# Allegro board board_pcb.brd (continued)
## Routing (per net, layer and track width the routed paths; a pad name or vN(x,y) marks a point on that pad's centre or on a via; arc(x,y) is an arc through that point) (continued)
BQ_STAT: length 9.2
  TOP w0.152: U133.1 60.15,24.72
  TOP w0.203: 60.15,24.72 60.15,25.25 60.3,25.4 v1(60.86,25.4)
  TOP w0.305: D134.1 67.27,27.01 v1(66.8,26.54)
  ART03 w0.305: v1(66.8,26.54) 66.04,25.78 63.25,25.78 62.87,25.4 v1(60.86,25.4)
BQ_TS: length 20.3
  TOP w0.305: R1853.2 C1998.1 52.81,15.52 58.19,10.13 R1516.2 62.23,9.17 R1738.1 R1518.2 62.26,6.58 62.47,6.36 J85.1
CC1: length 26.7
  TOP w0.152: v1(49.09,29.21) C1499.2 49.09,30.67 48.39,31.37 47.88,31.37 47.5,31.75 U117.15 ; v1(46.19,10.67) 46.06,10.54 D107.1 46.06,9.74 45.87,9.55 45.87,9.04 46.24,8.67 J73.A5
  BOTTOM w0.152: v1(49.09,29.21) 49.09,27.5 47.24,25.65 47.24,12.45 46.19,11.39 v1(46.19,10.67)
CC2: length 39.5
  TOP w0.152: v2(48.25,7.15) 48.25,7.1 47.99,6.85 J73.B5 ; U117.14 47,31.61 47.82,30.8 C1507.2 v1(47.82,29.21)
  BOTTOM w0.152: v2(48.25,7.15) 48.25,5.79 48.04,5.59 D106.1 47.66,4.83 42.8,4.83 41.91,5.71 41.91,8.76 43.81,10.67 44.83,10.67 46.61,12.45 46.61,28 v1(47.82,29.21)
CE_0: length 25
  TOP w0.305: 19.43,22.86 19.43,21.46 J76.1 18.92,16.38 18.92,4.34 18.57,3.99 16.59,3.99 J75.3
CE_1: length 27.6
  TOP w0.305: J76.6 10.03,14.61 8.26,14.61 4.45,18.41 4.45,31.88 6.48,33.91 U134.12
CHARGER_QON: length 44
  TOP w0.152: v1(43.94,46.48) 44.7,47.24 44.7,48.39 45.21,48.9 45.21,51.4 47.7,53.89 47.7,54.69 48.47,55.46 48.47,57.25 U1.D2 ; v1(51.44,24.89) 51.05,24.51 R1503.1 51.33,23.9 51.94,24.51 Q39.1
  ART08 w0.114: v1(43.94,46.48) 43.94,45.36 43.1,44.53 43.1,44.02 41.83,42.75 41.83,38.07 45.36,34.54 45.36,28.47 48.95,24.89 v1(51.44,24.89)
DEBUG_MS_RX: length 14.8
  TOP w0.152: S8.5 32.64,60.6 32.36,60.33 28.19,60.33 27.18,61.34 D114.1 26.16,61.72 24.26,61.72 22.61,60.07 22.61,59.94 21.97,59.31
DEBUG_MS_TX: length 17
  TOP w0.152: 19.43,59.31 20.7,60.58 22.48,60.58 24.26,62.36 25.4,62.36 26.04,62.99 26.04,63.63 D114.2 29.59,64.77 31.37,62.99 31.37,61.33
ETH_MDC: length 57.6
  TOP w0.152: U1.M2 v2(54.07,57.25) ; U3.24 13.67,74.34 13.84,74.17 13.84,72.77 12.19,71.12 12.19,68.96 13.59,67.56 31.75,67.56 32.77,66.55 32.77,64.52 33.78,63.5 33.78,62.61 34.67,61.72 35.31,61.72 v1(35.94,62.36)
  BOTTOM w0.152: v1(35.94,62.36) 35.94,61.06 38.58,58.42 43.93,58.42 44.7,57.65 50.3,57.65 50.47,57.48 50.47,57.02 50.65,56.85 53.44,56.85 53.84,57.25 v2(54.07,57.25)
ETH_MDIO: length 52.4
  TOP w0.152: U1.N3 54.87,58.05 v2(54.87,57.25) ; v1(34.8,62.36) 34.8,63.12 33.21,64.7 33.21,66.73 31.94,68.01 13.9,68.01 12.83,69.09 R1776.2
  BOTTOM w0.152: v1(34.8,62.36) 34.8,61.34 38.23,57.91 43.81,57.91 44.88,56.85 49.5,56.85 49.67,56.68 49.67,56.25 49.89,56.03 52.48,56.03 52.98,56.54 53.87,56.54 54.1,56.77 54.39,56.77 v2(54.87,57.25)
ETH_RMII_CLK: length 70.8
  TOP w0.152: R1783.2 25.68,72.24 26.67,71.25 26.67,70.74 27.05,70.36 28.28,70.36 28.43,70.21 28.43,69.24 28.58,69.09 28.89,69.09 29.04,69.24 29.04,70.21 29.19,70.36 29.5,70.36 29.65,70.21 29.65,69.24 29.8,69.09 30.11,69.09 30.26,69.24 30.26,70.21 30.41,70.36 30.72,70.36 30.87,70.21 30.87,69.24 31.02,69.09 31.33,69.09 31.48,69.24 31.48,70.21 31.63,70.36 31.94,70.36 32.09,70.21 32.09,69.24 32.24,69.09 32.55,69.09 32.7,69.24 32.7,70.21 32.85,70.36 33.16,70.36 33.31,70.21 33.31,69.24 33.46,69.09 33.76,69.09 33.92,69.24 33.92,70.21 34.07,70.36 34.39,70.36 34.54,70.21 34.54,69.96 34.7,69.8 36.58,69.8 36.73,69.65 36.73,69.35 36.58,69.19 34.7,69.19 34.54,69.04 34.54,68.74 34.7,68.59 36.58,68.59 36.73,68.43 36.73,68.13 36.58,67.98 34.7,67.98 34.54,67.82 34.54,65.68 35.18,65.04 35.4,65.04 36.76,66.4 36.97,66.4 37.19,66.19 37.19,65.97 35.83,64.61 35.83,64.4 36.05,64.18 36.26,64.18 37.62,65.54 37.84,65.54 38.05,65.32 38.05,65.11 36.69,63.75 36.69,63.53 37.21,63.02 v1(37.21,62.36) ; R1783.2 R1778.2 ; R1783.2 26.14,73.53 26.29,73.38 26.29,73.03 26.6,72.71 X5.3
  BOTTOM w0.152: R1782.2 51.66,57.94 51.16,58.45 45.09,58.45 44.64,58.89 41.69,58.89 41.24,59.35 41.02,59.35 40.6,58.93 40.39,58.93 40.17,59.14 40.17,59.36 40.59,59.78 40.59,59.99 40.01,60.58 38.99,60.58 38.28,61.28 38.07,61.28 37.52,60.74 37.31,60.74 37.09,60.95 37.09,61.17 37.64,61.71 37.64,61.93 v1(37.21,62.36)
ETH_RMII_RXD0: length 74.5
  TOP w0.152: R1774.2 v1(15.88,68.96) ; v1(40.77,45.85) 41.91,45.85 42.42,45.34 43.32,45.34 43.48,45.19 43.48,44.93 43.63,44.78 43.93,44.78 44.09,44.93 44.09,45.19 44.24,45.34 44.54,45.34 44.7,45.19 44.7,44.93 44.85,44.78 45.15,44.78 45.31,44.93 45.31,45.19 45.46,45.34 45.76,45.34 45.92,45.19 45.92,44.93 46.07,44.78 46.37,44.78 46.52,44.93 46.52,45.19 46.68,45.34 46.98,45.34 47.13,45.19 47.13,44.93 47.29,44.78 47.59,44.78 47.74,44.93 47.74,45.19 47.9,45.34 48.2,45.34 48.35,45.19 48.35,44.93 48.51,44.78 48.81,44.78 48.96,44.93 48.96,45.19 49.12,45.34 49.42,45.34 49.57,45.19 49.57,44.93 49.73,44.78 50.03,44.78 50.18,44.93 50.18,45.19 50.33,45.34 50.64,45.34 50.79,45.19 50.79,44.93 50.94,44.78 51.25,44.78 51.4,44.93 51.4,45.43 54.1,48.13 54.1,52.2 54.99,53.09 55.75,53.09 55.88,52.96 57.53,52.96 58.07,53.5 58.07,58.85 U1.T4
  BOTTOM w0.152: v1(40.77,45.85) 40.26,46.35 39.24,46.35 38.77,46.82 38.77,48.81 30.61,56.97 30.61,58.8 30.35,59.05 28.57,59.05 26.04,61.59 26.04,65.58 24.38,67.23 17.6,67.23 v1(15.88,68.96)
ETH_RMII_RXD1: length 75.3
  TOP w0.152: R1775.2 v1(14.86,68.96) ; U1.U4 59.41,58.31 59.41,56.24 58.8,55.63 58.8,47.5 58.42,47.12 54.28,47.12 51.16,43.99 45.03,43.99 v1(44.96,44.07)
  BOTTOM w0.152: v1(14.86,68.96) 15.75,69.85 25.32,69.85 25.68,69.49 25.68,68.63 28.24,66.07 28.24,62.26 29.51,60.99 31.98,60.99 35.05,57.91 35.05,54.23 40.26,49.02 40.89,49.02 41.91,48.01 41.91,47.75 42.61,47.05 43.12,47.05 43.38,46.79 43.38,45.77 44.96,44.2 v1(44.96,44.07)
ETH_RMII_RXDV: length 73.4
  TOP w0.152: R1777.2 v1(22.99,69.22) ; v1(43.69,44.07) 44.32,43.43 51.23,43.43 54.43,46.63 58.78,46.63 59.23,47.09 59.23,54.53 59.94,55.24 59.94,55.47 60.1,55.62 60.81,55.62 60.96,55.78 60.96,56.08 60.81,56.23 60.1,56.23 59.94,56.39 59.94,56.69 60.1,56.84 60.81,56.84 60.96,57 60.96,57.3 60.81,57.45 60.1,57.45 59.94,57.61 59.94,58.55 58.84,59.65 57.27,59.65 U1.R5
  BOTTOM w0.152: v1(43.69,44.07) 42.04,45.72 42.04,46.35 41.4,46.99 41.4,48.01 40.77,48.64 40.13,48.64 34.29,54.48 34.29,57.91 31.88,60.33 29.34,60.33 27.57,62.09 27.57,65.75 24.87,68.45 23.14,68.45 22.99,68.61 v1(22.99,69.22)
ETH_RMII_TX_EN: length 77.1
  TOP w0.152: v1(11.68,75.69) 11.83,75.84 U3.21 ; v2(42.16,62.36) 43.18,63.37 44.45,63.37 44.72,63.65 46.07,63.65 U1.B9
  BOTTOM w0.152: v2(42.16,62.36) 40.39,62.36 38.23,64.52 32.41,64.52 30.73,66.19 30.73,66.78 30.89,66.94 32.46,66.94 32.61,67.09 32.61,67.39 32.46,67.55 30.89,67.55 30.73,67.7 30.73,68 30.89,68.16 32.46,68.16 32.61,68.31 32.61,68.61 32.46,68.76 30.89,68.76 30.73,68.92 30.73,69.22 30.89,69.37 32.46,69.37 32.61,69.53 32.61,69.83 32.46,69.98 30.89,69.98 30.73,70.14 30.73,70.33 30.58,70.48 29.06,70.48 27.84,71.7 26.59,71.7 26.34,71.96 26.34,74.14 26.06,74.42 22.85,74.42 22.7,74.57 22.7,76.17 22.55,76.33 22.24,76.33 22.09,76.17 22.09,74.57 21.94,74.42 21.63,74.42 21.48,74.57 21.48,76.17 20.19,77.47 18.82,77.47 18.67,77.32 18.67,76.86 18.51,76.71 18.21,76.71 18.06,76.86 18.06,77.32 17.9,77.47 17.48,77.47 17.33,77.32 17.33,75.84 17.17,75.69 16.87,75.69 16.72,75.84 16.72,77.32 16.56,77.47 16.26,77.47 16.11,77.32 16.11,75.84 15.95,75.69 15.65,75.69 15.5,75.84 15.5,77.32 15.34,77.47 15.04,77.47 14.89,77.32 14.89,75.84 14.73,75.69 14.43,75.69 14.28,75.84 14.28,77.32 14.12,77.47 13.82,77.47 13.67,77.32 13.67,75.84 13.52,75.69 13.21,75.69 13.06,75.84 13.06,77.32 12.91,77.47 12.6,77.47 12.45,77.32 12.45,75.84 12.3,75.69 v1(11.68,75.69)
ETH_RMII_TXD0: length 74.7
  TOP w0.152: U1.D9 47.67,62.85 44.18,62.85 v2(43.69,62.36) ; R1787.1 v1(8.76,75.95)
  BOTTOM w0.152: v1(8.76,75.95) 9.37,75.34 9.37,74.47 9.55,74.3 9.85,74.3 10.03,74.47 10.03,77.24 10.18,77.39 10.48,77.39 10.64,77.24 10.64,74.47 10.79,74.32 11.07,74.32 11.23,74.17 11.23,73.58 11.38,73.43 11.68,73.43 11.84,73.58 11.84,74.17 11.99,74.32 12.4,74.32 12.57,74.14 12.57,72.92 12.73,72.77 13.07,72.77 13.23,72.92 13.23,74.85 13.38,75.01 13.68,75.01 13.84,74.85 13.84,72.92 13.99,72.77 14.29,72.77 14.45,72.92 14.45,74.85 14.6,75.01 14.9,75.01 15.06,74.85 15.06,72.92 15.21,72.77 19.48,72.77 19.63,72.92 19.63,74.55 19.78,74.7 20.09,74.7 20.24,74.55 20.24,72.92 20.39,72.77 20.95,72.77 21.1,72.92 21.1,73.51 21.26,73.66 21.56,73.66 21.71,73.51 21.71,72.92 21.87,72.77 22.17,72.77 22.32,72.92 22.32,73.51 22.48,73.66 22.78,73.66 22.93,73.51 22.93,72.92 23.08,72.77 23.39,72.77 23.54,72.92 23.54,73.51 23.69,73.66 24,73.66 24.15,73.51 24.15,72.92 24.3,72.77 24.61,72.77 24.76,72.92 24.76,73.51 24.91,73.66 25.22,73.66 25.37,73.51 25.37,72.75 25.55,72.57 25.68,72.57 25.83,72.42 25.83,71.73 27.4,70.16 27.62,70.16 27.79,70.34 28.01,70.34 28.23,70.12 28.23,69.91 28.05,69.73 28.05,69.51 30.1,67.46 30.1,65.91 32.26,63.75 38.23,63.75 40.18,61.8 42.47,61.8 43.03,62.36 v2(43.69,62.36)
ETH_RMII_TXD1: length 73.5
  TOP w0.152: v1(42.16,78.99) 42.16,78.36 44.63,75.9 47.73,75.9 48.59,75.03 57.56,75.03 60.07,72.52 60.07,68.85 U1.U14 ; R1848.1 v1(8.76,77.98)
  BOTTOM w0.152: v1(42.16,78.99) 40.34,78.99 36.78,75.44 36.53,75.44 36.38,75.29 36.38,73.79 36.22,73.63 35.92,73.63 35.77,73.79 35.77,75.29 35.61,75.44 35.31,75.44 35.16,75.29 35.16,73.79 35,73.63 34.7,73.63 34.55,73.79 34.55,75.29 34.39,75.44 34.09,75.44 33.94,75.29 33.94,73.79 33.78,73.63 33.48,73.63 33.33,73.79 33.33,75.29 33.17,75.44 24.87,75.44 23.27,77.04 22.15,77.04 21.15,78.04 8.83,78.04 v1(8.76,77.98)
ETH_RMII_TXD1-1: length 74.4
  TOP w0.152: U1.D8 v2(47.67,62.05) ; R1788.1 v1(8.76,76.96)
  BOTTOM w0.152: v2(47.67,62.05) 47.18,62.53 44.86,62.53 44.15,61.82 43.69,61.82 43.21,61.34 39.88,61.34 38.1,63.12 33.98,63.12 33.82,62.97 33.82,62.13 33.67,61.98 33.37,61.98 33.22,62.13 33.22,62.97 33.06,63.12 32,63.12 29.24,65.89 29.24,67.28 29.04,67.48 28.82,67.48 28.53,67.19 28.31,67.19 28.1,67.41 28.1,67.62 28.39,67.91 28.39,68.13 28.17,68.35 27.96,68.35 27.67,68.05 27.45,68.05 27.23,68.27 27.23,68.48 27.53,68.78 27.53,68.99 25.4,71.12 24.36,71.12 24.21,71.27 24.21,71.93 24.06,72.09 23.75,72.09 23.6,71.93 23.6,71.27 23.45,71.12 23.15,71.12 22.99,71.27 22.99,71.93 22.84,72.09 22.54,72.09 22.38,71.93 22.38,71.27 22.23,71.12 21.93,71.12 21.77,71.27 21.77,71.93 21.62,72.09 21.32,72.09 21.16,71.93 21.16,71.27 21.01,71.12 20.71,71.12 20.55,71.27 20.55,71.93 20.4,72.09 20.1,72.09 19.94,71.93 19.94,71.27 19.79,71.12 19.49,71.12 19.34,71.27 19.34,71.93 19.18,72.09 18.88,72.09 18.73,71.93 18.73,71.27 18.57,71.12 18.27,71.12 18.12,71.27 18.12,71.93 17.96,72.09 17.66,72.09 17.51,71.93 17.51,71.27 17.35,71.12 17.05,71.12 16.9,71.27 16.9,71.93 16.74,72.09 16.44,72.09 16.29,71.93 16.29,71.27 16.13,71.12 15.83,71.12 15.68,71.27 15.68,71.93 15.53,72.09 15.22,72.09 15.07,71.93 15.07,71.27 14.92,71.12 14.61,71.12 14.46,71.27 14.46,71.93 14.31,72.09 14,72.09 13.85,71.93 13.85,71.27 13.7,71.12 13.39,71.12 13.24,71.27 13.24,71.93 13.09,72.09 12.78,72.09 12.63,71.93 12.63,71.27 12.48,71.12 9.3,71.12 9.14,71.27 9.14,71.73 9.3,71.88 9.75,71.88 9.91,72.03 9.91,72.34 9.75,72.49 9.3,72.49 9.14,72.64 9.14,72.94 9.3,73.1 9.75,73.1 9.91,73.25 9.91,73.55 9.75,73.71 9.3,73.71 9.14,73.86 9.14,73.95 8.93,74.17 8.51,74.17 8.13,74.55 8.13,76.33 v1(8.76,76.96)
FAULT: length 43.1
  TOP w0.152: U1.E5 v2(48.47,59.65) ; U117.9 v1(44.71,34.41)
  ART08 w0.114: v1(44.71,34.41) 41.3,37.82 41.3,43.31 42.62,44.63 42.62,45.52 41.02,47.12 39.62,47.12 38.72,48.02 38.72,60.24 39.83,61.34 44.15,61.34 44.32,61.16 46.3,61.16 46.62,60.85 47.84,60.85 48.06,60.63 48.06,60.06 v2(48.47,59.65)
FET_GATE: length 10.9
  TOP w0.305: R1495.2 49.28,26.31 R1381.1 48.92,25.3 48.64,25.02 48.64,24.74 48.19,24.28 D97.2
  TOP w0.508: Q22.4 46.23,27.56 46.74,27.05 46.74,25.4 46.35,25.02 ; 46.35,25.02 Q22.2 ; 46.35,25.02 46.61,24.77 46.61,24.41 46.74,24.28 D97.2
FET_SRC: length 14.1
  TOP w0.305: D97.1 47.88,27.91 R1495.1
  TOP w0.508: Q22.1 43.69,23.75 43.18,24.26 43.18,25.97 43.5,26.29 ; 43.5,26.29 43.18,26.61 43.18,27.94 43.69,28.45 47.09,28.45 D97.1 ; 43.5,26.29 Q22.3
FMC_A0: length 46.6
  TOP w0.152: U2.G8 v2(68.48,62.43) ; U1.G4 v2(50.07,58.85)
  ART06 w0.099: v2(50.07,58.85) 50.07,60.15 50.98,61.06 54.43,61.06 54.68,60.81 54.68,60.56 54.83,60.41 55.09,60.41 55.5,60 55.5,59.86 55.36,59.72 55.36,59.58 55.5,59.44 55.64,59.44 55.78,59.58 55.92,59.58 56.24,59.26 56.87,59.26 56.97,59.36 56.97,59.59 57.07,59.69 57.27,59.69 57.36,59.59 57.36,59.36 57.46,59.26 57.61,59.26 57.71,59.16 57.71,58.62 57.81,58.52 57.99,58.52 58.09,58.62 58.09,59.59 58.19,59.69 58.38,59.69 58.48,59.59 58.48,58.62 58.58,58.52 58.78,58.52 58.88,58.62 58.88,59.59 58.98,59.69 59.18,59.69 59.28,59.59 59.28,58.62 59.38,58.52 59.57,58.52 59.67,58.62 59.67,59.46 59.77,59.56 59.97,59.56 60.07,59.46 60.07,58.14 60.17,58.04 61.26,58.04 61.36,58.14 61.36,59.08 61.46,59.18 61.66,59.18 61.76,59.08 61.76,58.14 61.85,58.04 62.05,58.04 62.15,58.14 62.15,59.08 62.25,59.18 62.45,59.18 62.55,59.08 62.55,58.14 62.65,58.04 62.85,58.04 62.94,58.14 62.94,59.08 63.04,59.18 63.24,59.18 63.34,59.08 63.34,58.14 63.44,58.04 63.64,58.04 63.74,58.14 63.74,59.08 63.84,59.18 64.03,59.18 64.13,59.08 64.13,58.14 64.23,58.04 64.43,58.04 64.53,58.14 64.53,59.08 64.63,59.18 64.83,59.18 64.93,59.08 64.93,58.14 65.02,58.04 65.22,58.04 65.32,58.14 65.32,59.08 65.42,59.18 65.62,59.18 65.72,59.08 65.72,58.14 65.82,58.04 66.02,58.04 66.14,58.16 66.14,58.65 66.29,58.8 67.72,58.8 67.82,58.9 67.82,61.76 v2(68.48,62.43)
FMC_A1: length 46.5
  TOP w0.152: U1.G3 v2(50.07,58.05) ; U2.G9 v2(66.89,62.43)
  ART06 w0.099: v2(50.07,58.05) 49.66,58.46 49.66,60.35 50.77,61.47 54.66,61.47 55.31,60.82 56.77,60.82 56.87,60.72 56.87,60.3 57.1,60.07 60.07,60.07 60.63,59.51 61.14,59.51 61.34,59.71 61.34,61.06 61.44,61.16 61.64,61.16 61.74,61.06 61.74,59.71 61.84,59.61 62.03,59.61 62.13,59.71 62.13,61.11 62.23,61.21 62.43,61.21 62.53,61.11 62.53,59.71 62.63,59.61 62.83,59.61 62.93,59.71 62.93,61.11 63.03,61.21 63.22,61.21 63.32,61.11 63.32,59.71 63.42,59.61 63.62,59.61 63.72,59.71 63.72,61.11 63.82,61.21 64.02,61.21 64.11,61.11 64.11,59.71 64.21,59.61 64.41,59.61 64.51,59.71 64.51,61.11 64.61,61.21 64.81,61.21 64.91,61.11 64.91,59.71 65.01,59.61 65.2,59.61 65.3,59.71 65.3,61.11 65.4,61.21 65.6,61.21 65.7,61.11 65.7,59.71 65.8,59.61 66,59.61 66.1,59.71 66.1,61.11 66.2,61.21 66.39,61.21 66.49,61.11 66.49,59.71 66.59,59.61 67.23,59.61 67.44,59.82 67.44,61.88 v2(66.89,62.43)
FMC_A2: length 46.5
  TOP w0.152: v2(69.28,60.83) 69.28,61.63 U2.F7 ; U1.G1 v2(50.07,56.45)
  ART06 w0.099: v2(69.28,60.83) 69.86,60.83 69.96,60.93 69.96,61.29 70.06,61.39 70.26,61.39 70.36,61.29 70.36,60.93 70.46,60.83 71.02,60.83 71.12,60.73 71.12,56.08 71.02,55.98 69.74,55.98 69.34,55.58 55.09,55.58 54.99,55.67 54.99,56.37 54.89,56.47 53.85,56.47 53.75,56.57 53.75,56.76 53.85,56.86 55.16,56.86 55.5,57.2 55.58,57.2 55.73,57.35 55.73,57.55 55.63,57.65 54.58,57.65 54.48,57.74 54.48,57.94 54.58,58.04 55.65,58.04 55.75,58.14 55.75,58.34 55.65,58.44 54.58,58.44 54.48,58.54 54.48,58.73 54.58,58.83 55.15,58.83 55.24,58.93 55.24,59.13 55.15,59.23 54.58,59.23 54.48,59.33 54.48,60.15 54,60.63 53.76,60.63 53.66,60.53 53.66,60.35 53.56,60.25 53.36,60.25 53.27,60.35 53.27,60.53 53.17,60.63 51.21,60.63 50.47,59.89 50.47,56.55 50.37,56.45 v2(50.07,56.45)
FMC_A3: length 46.6
  TOP w0.152: U2.F3 v2(71.69,61.63) ; U1.H4 v2(50.87,58.85)
  ART06 w0.099: v2(50.87,58.85) 51.48,59.46 51.48,59.6 51.19,59.89 51.19,60.03 51.33,60.17 51.47,60.17 51.76,59.88 51.9,59.88 52.07,60.05 52.73,60.05 52.86,59.92 52.86,55.98 53.09,55.75 54.18,55.75 54.76,55.17 58.18,55.17 58.28,55.07 58.28,54.84 58.38,54.74 58.57,54.74 58.67,54.84 58.67,55.07 58.77,55.17 58.97,55.17 59.07,55.07 59.07,54.84 59.17,54.74 59.37,54.74 59.47,54.84 59.47,55.07 59.57,55.17 59.76,55.17 59.86,55.07 59.86,54.84 59.96,54.74 60.16,54.74 60.26,54.84 60.26,55.07 60.36,55.17 60.56,55.17 60.65,55.07 60.65,54.84 60.75,54.74 60.95,54.74 61.05,54.84 61.05,55.07 61.15,55.17 61.35,55.17 61.45,55.07 61.45,54.84 61.55,54.74 61.74,54.74 61.84,54.84 61.84,55.07 61.94,55.17 62.14,55.17 62.24,55.07 62.24,54.84 62.34,54.74 62.54,54.74 62.64,54.84 62.64,55.07 62.73,55.17 62.93,55.17 63.03,55.07 63.03,54.84 63.13,54.74 63.33,54.74 63.43,54.84 63.43,55.07 63.53,55.17 63.73,55.17 63.82,55.07 63.82,54.84 63.92,54.74 64.12,54.74 64.22,54.84 64.22,55.07 64.32,55.17 64.52,55.17 64.62,55.07 64.62,54.84 64.72,54.74 64.91,54.74 65.01,54.84 65.01,55.07 65.11,55.17 65.31,55.17 65.41,55.07 65.41,54.84 65.51,54.74 65.71,54.74 65.81,54.84 65.81,55.07 65.9,55.17 66.1,55.17 66.2,55.07 66.2,54.84 66.3,54.74 66.5,54.74 66.6,54.84 66.6,55.07 66.7,55.17 66.9,55.17 66.99,55.07 66.99,54.84 67.09,54.74 67.29,54.74 67.39,54.84 67.39,55.07 67.49,55.17 67.69,55.17 67.79,55.07 67.79,54.84 67.89,54.74 68.08,54.74 68.18,54.84 68.18,55.07 68.28,55.17 68.48,55.17 68.58,55.07 68.58,54.84 68.68,54.74 68.88,54.74 68.98,54.84 68.98,55.07 69.07,55.17 69.57,55.17 69.93,55.52 70.21,55.52 70.31,55.43 70.31,55.24 70.41,55.14 70.6,55.14 70.7,55.24 70.7,55.43 70.8,55.52 71.98,55.52 72.11,55.65 72.11,55.95 72.01,56.04 71.65,56.04 71.55,56.14 71.55,56.34 71.65,56.44 72.01,56.44 72.11,56.54 72.11,56.74 72.01,56.84 71.65,56.84 71.55,56.94 71.55,57.13 71.65,57.23 72.01,57.23 72.11,57.33 72.11,60.35 72.01,60.45 71.63,60.45 71.53,60.55 71.53,60.74 71.63,60.84 72.01,60.84 72.11,60.94 72.11,61.2 v2(71.69,61.63)
FMC_A4: length 46.6
  TOP w0.152: U1.J5 v2(52.47,59.65) ; U2.G1 v2(74.08,62.43)
  ART06 w0.099: v2(74.08,62.43) 73.66,62 73.66,55.37 72.26,53.98 72.26,52.96 72.01,52.7 70.23,52.7 70,52.47 69.35,52.47 69.25,52.57 69.25,52.66 69.15,52.76 68.95,52.76 68.85,52.66 68.85,52.57 68.75,52.47 68.55,52.47 68.46,52.57 68.46,52.66 68.36,52.76 68.16,52.76 68.06,52.66 68.06,52.57 67.96,52.47 67.76,52.47 67.66,52.57 67.66,52.66 67.56,52.76 67.37,52.76 67.27,52.66 67.27,52.57 67.17,52.47 66.97,52.47 66.87,52.57 66.87,52.66 66.77,52.76 66.57,52.76 66.47,52.66 66.47,52.57 66.38,52.47 66.18,52.47 66.08,52.57 66.08,52.66 65.98,52.76 65.78,52.76 65.68,52.66 65.68,52.57 65.58,52.47 63.1,52.47 63,52.57 63,53.09 62.9,53.19 62.7,53.19 62.6,53.09 62.6,52.57 62.5,52.47 62.31,52.47 62.21,52.57 62.21,53.09 62.11,53.19 61.91,53.19 61.81,53.09 61.81,52.57 61.71,52.47 61.51,52.47 61.41,52.57 61.41,53.09 61.32,53.19 61.12,53.19 61.02,53.09 61.02,52.57 60.92,52.47 60.72,52.47 60.62,52.57 60.62,53.09 60.52,53.19 60.32,53.19 60.23,53.09 60.23,52.57 60.13,52.47 59.93,52.47 59.83,52.57 59.83,53.09 59.73,53.19 59.53,53.19 59.43,53.09 59.43,52.57 59.33,52.47 59.14,52.47 59.04,52.57 59.04,53.09 58.94,53.19 58.74,53.19 58.64,53.09 58.64,52.8 58.54,52.7 58.14,52.7 58.04,52.8 58.04,53.72 57.56,54.2 53.44,54.2 51.69,55.96 51.69,58.87 v2(52.47,59.65)
FMC_A5: length 46.6
  TOP w0.152: U2.G2 v2(73.28,62.43) ; U1.J4 v2(52.47,58.85)
  ART06 w0.099: v2(73.28,62.43) 73.03,62.17 73.03,57.34 72.93,57.24 72.74,57.24 72.64,57.14 72.64,56.94 72.74,56.85 72.93,56.85 73.03,56.75 73.03,56.55 72.93,56.45 72.74,56.45 72.64,56.35 72.64,56.15 72.74,56.05 72.93,56.05 73.03,55.95 73.03,55.5 72.52,54.99 71.27,54.99 71.09,54.81 71.09,54.15 70.87,53.92 70.28,53.92 69.98,53.62 69.79,53.62 69.69,53.72 69.69,54.59 69.59,54.69 69.39,54.69 69.3,54.59 69.3,53.72 69.2,53.62 69,53.62 68.9,53.52 68.9,53.41 68.8,53.31 68.61,53.31 68.51,53.41 68.51,53.52 68.41,53.62 68.21,53.62 68.11,53.52 68.11,53.41 68.01,53.31 67.81,53.31 67.71,53.41 67.71,53.52 67.61,53.62 67.42,53.62 67.32,53.52 67.32,53.41 67.22,53.31 67.02,53.31 66.92,53.41 66.92,53.52 66.82,53.62 66.62,53.62 66.53,53.52 66.53,53.41 66.43,53.31 66.23,53.31 66.13,53.41 66.13,53.52 66.03,53.62 65.83,53.62 65.73,53.52 65.73,53.41 65.63,53.31 65.44,53.31 65.34,53.41 65.34,53.52 65.24,53.62 63.24,53.62 63.14,53.72 63.14,54.23 63.04,54.33 62.85,54.33 62.75,54.23 62.75,53.72 62.65,53.62 62.45,53.62 62.35,53.72 62.35,54.23 62.25,54.33 62.05,54.33 61.95,54.23 61.95,53.72 61.86,53.62 61.66,53.62 61.56,53.72 61.56,54.23 61.46,54.33 61.26,54.33 61.16,54.23 61.16,53.72 61.06,53.62 60.87,53.62 60.77,53.72 60.77,54.23 60.67,54.33 60.47,54.33 60.37,54.23 60.37,53.72 60.27,53.62 59.35,53.62 59.25,53.72 59.25,54.23 59.15,54.33 58.95,54.33 58.86,54.23 58.86,53.72 58.76,53.62 58.56,53.62 58.46,53.72 58.46,54.06 57.86,54.66 53.57,54.66 52.07,56.16 52.07,56.34 52.17,56.44 52.43,56.44 52.53,56.54 52.53,56.74 52.43,56.84 52.17,56.84 52.07,56.94 52.07,57.13 52.17,57.23 52.43,57.23 52.53,57.33 52.53,57.53 52.43,57.63 52.17,57.63 52.07,57.73 52.07,58.45 v2(52.47,58.85)
FMC_A6: length 46.6
  TOP w0.152: U1.R7 v2(57.27,61.25) ; U2.G3 v2(71.69,62.43)
  ART06 w0.099: v2(71.69,62.43) 71.35,62.43 71.25,62.33 71.25,61.26 71.15,61.16 70.86,61.16 70.76,61.26 70.76,61.9 70.67,62 70.43,62 70.33,62.1 70.33,62.3 70.43,62.4 70.67,62.4 70.76,62.5 70.76,62.71 70.25,63.23 70.25,63.37 70.55,63.67 70.55,63.81 70.41,63.95 70.27,63.95 69.97,63.65 69.83,63.65 69.47,64.01 69.06,64.01 68.35,64.72 68.21,64.72 67.91,64.41 67.77,64.41 67.63,64.55 67.63,64.69 67.75,64.82 67.75,64.96 67.28,65.43 67.28,67.11 67.38,67.21 67.62,67.21 67.72,67.31 67.72,67.51 67.62,67.6 67.38,67.6 67.28,67.7 67.28,68.76 67.19,68.86 67.03,68.86 66.93,68.96 66.93,69.14 66.83,69.24 66.63,69.24 66.53,69.14 66.53,68.96 66.43,68.86 66.23,68.86 66.13,68.96 66.13,69.14 66.04,69.24 65.84,69.24 65.74,69.14 65.74,68.96 65.64,68.86 65.44,68.86 65.34,68.96 65.34,69.14 65.24,69.24 65.05,69.24 64.95,69.14 64.95,68.96 64.85,68.86 64.65,68.86 64.55,68.96 64.55,69.14 64.45,69.24 64.25,69.24 64.15,69.14 64.15,68.96 64.05,68.86 63.86,68.86 63.76,68.96 63.76,69.14 63.66,69.24 63.46,69.24 63.36,69.14 63.36,68.96 63.26,68.86 63.06,68.86 62.97,68.96 62.97,69.14 62.87,69.24 62.67,69.24 62.57,69.14 62.57,68.96 62.47,68.86 62.27,68.86 62.17,68.96 62.17,69.14 62.07,69.24 61.88,69.24 61.78,69.14 61.78,68.96 61.68,68.86 61.48,68.86 61.38,68.96 61.38,69.14 61.28,69.24 61.08,69.24 60.98,69.14 60.98,68.96 60.88,68.86 60.69,68.86 60.59,68.96 60.59,69.14 60.49,69.24 60.29,69.24 60.19,69.14 60.19,68.96 60.09,68.86 59.89,68.86 59.8,68.96 59.8,69.14 59.7,69.24 59.5,69.24 59.4,69.14 59.4,68.96 59.3,68.86 57.75,68.86 57.65,68.96 57.65,69.19 57.55,69.29 57.35,69.29 57.25,69.19 57.25,68.96 57.15,68.86 56.96,68.86 56.86,68.96 56.86,69.19 56.76,69.29 56.56,69.29 56.46,69.19 56.46,68.96 56.36,68.86 55.37,68.86 55.24,68.73 55.24,66.57 55.37,66.45 58.37,66.45 58.47,66.35 58.47,64.26 58.67,64.06 59.18,64.06 59.31,63.93 59.31,63.5 58.42,62.61 58.04,62.61 57.66,62.23 57.66,61.85 57.27,61.46 v2(57.27,61.25)
FMC_A7: length 46.6
  TOP w0.152: U1.P7 v2(56.47,61.25) ; U2.H1 v2(74.25,63.63)
  ART06 w0.099: v2(74.25,63.63) 73.84,63.63 73.74,63.53 73.74,62.96 73.64,62.87 73.45,62.87 73.35,62.96 73.35,63.53 73.25,63.63 73.05,63.63 72.95,63.53 72.95,62.96 72.85,62.87 72.65,62.87 72.55,62.96 72.55,63.53 72.46,63.63 72.26,63.63 72.16,63.53 72.16,62.96 72.06,62.87 71.86,62.87 71.76,62.96 71.76,63.53 71.66,63.63 71.47,63.63 71.37,63.53 71.37,62.96 71.27,62.87 71.07,62.87 70.97,62.96 70.97,64.21 70.76,64.41 69.06,64.41 68.33,65.15 68.33,65.61 67.82,66.12 67.82,66.9 68.07,67.16 68.07,67.82 67.97,67.92 67.76,67.92 67.67,68.02 67.67,68.22 67.76,68.32 67.97,68.32 68.07,68.42 68.07,68.62 67.04,69.65 57.75,69.65 57.65,69.75 57.65,70.11 57.55,70.21 57.35,70.21 57.25,70.11 57.25,69.75 57.16,69.65 56.96,69.65 56.86,69.75 56.86,70.11 56.76,70.21 56.56,70.21 56.46,70.11 56.46,69.75 56.36,69.65 54.58,69.65 54.48,69.55 54.48,65.76 54.58,65.66 57.51,65.66 57.66,65.51 57.66,64.26 57.89,64.03 58.29,64.03 58.45,63.88 58.45,63.47 58.14,63.17 57.73,63.17 56.9,62.33 56.9,61.35 56.8,61.25 v2(56.47,61.25)
FMC_A8: length 46.7
  TOP w0.152: U1.P8 v2(56.47,62.05) ; U2.H2 v2(72.49,64.03)
  ART06 w0.099: v2(56.47,62.05) 56.47,62.31 57.66,63.5 57.66,63.88 57.48,64.06 57.1,64.06 56.9,64.26 56.9,64.64 56.69,64.85 54.7,64.85 54.6,64.75 54.6,64.46 54.5,64.36 54.3,64.36 54.2,64.46 54.2,64.75 54.1,64.85 53.92,64.85 53.67,65.1 53.67,65.83 53.57,65.93 53.34,65.93 53.24,66.03 53.24,66.23 53.34,66.33 53.57,66.33 53.67,66.43 53.67,68.9 53.57,69 53.31,69 53.21,69.1 53.21,69.3 53.31,69.4 53.72,69.4 53.82,69.5 53.82,69.7 53.72,69.8 53.31,69.8 53.21,69.89 53.21,70.09 53.31,70.19 53.57,70.19 53.67,70.29 53.67,70.56 53.77,70.66 53.97,70.66 54.07,70.76 54.07,71.05 54.17,71.15 54.37,71.15 54.47,71.05 54.47,70.76 54.57,70.66 54.76,70.66 54.86,70.76 54.86,71.05 54.96,71.15 55.16,71.15 55.26,71.05 55.26,70.76 55.36,70.66 55.56,70.66 55.65,70.76 55.65,71.05 55.75,71.15 55.95,71.15 56.05,71.05 56.05,70.76 56.15,70.66 56.35,70.66 56.45,70.76 56.45,71.05 56.55,71.15 56.74,71.15 56.84,71.05 56.84,70.76 56.94,70.66 57.14,70.66 57.24,70.76 57.24,71.05 57.34,71.15 57.54,71.15 57.64,71.05 57.64,70.76 57.74,70.66 58.01,70.66 58.11,70.76 58.11,71.05 58.21,71.15 58.41,71.15 58.51,71.05 58.51,70.76 58.61,70.66 58.78,70.66 59.39,70.05 68.81,70.05 68.91,69.95 68.91,67.01 68.71,66.8 68.2,66.8 68.07,66.67 68.07,66.27 68.58,65.76 68.58,65.41 69.24,64.75 70.94,64.75 71.3,64.39 72.39,64.39 72.49,64.29 v2(72.49,64.03)
FMC_A9: length 46.6
  TOP w0.152: U1.R9 v2(57.27,63.65) ; U2.J3 v2(71.69,64.83)
  ART06 w0.099: v2(57.27,63.65) 57,63.65 56.62,64.03 53.82,64.03 53.67,64.19 53.67,64.57 52.88,65.35 52.88,70.43 53.34,70.89 53.34,71.32 53.62,71.6 53.85,71.6 53.95,71.7 53.95,72.29 54.04,72.39 54.24,72.39 54.34,72.29 54.34,71.7 54.44,71.6 54.64,71.6 54.74,71.7 54.74,72.29 54.84,72.39 55.04,72.39 55.13,72.29 55.13,71.7 55.23,71.6 55.46,71.6 55.56,71.7 55.56,71.86 55.66,71.96 55.86,71.96 55.96,71.86 55.96,71.7 56.06,71.6 56.38,71.6 56.48,71.7 56.48,72.32 56.58,72.42 56.78,72.42 56.88,72.32 56.88,71.7 56.97,71.6 57.17,71.6 57.27,71.7 57.27,72.32 57.37,72.42 57.57,72.42 57.67,72.32 57.67,71.7 57.77,71.6 57.97,71.6 58.06,71.7 58.06,72.32 58.16,72.42 58.36,72.42 58.46,72.32 58.46,71.7 58.56,71.6 59.03,71.6 59.13,71.5 59.13,70.92 59.56,70.48 69.6,70.48 69.7,70.39 69.7,67.41 68.88,66.6 68.88,65.48 69.22,65.15 69.57,65.15 69.67,65.25 69.67,65.61 69.77,65.71 69.96,65.71 70.06,65.61 70.06,65.25 70.16,65.15 71.59,65.15 71.69,65.05 v2(71.69,64.83)
FMC_A10: length 46.6
  TOP w0.152: U1.T8 v2(58.07,62.05) ; U2.G7 v2(69.28,62.43)
  ART06 w0.099: v2(69.28,62.43) 68.87,62.84 67.92,62.84 67.82,62.74 67.82,62.43 67.73,62.33 67.53,62.33 67.43,62.43 67.43,62.74 67.33,62.84 66.62,62.84 66.5,62.71 66.5,61.77 66.4,61.67 66.12,61.67 66.02,61.77 66.02,63.73 65.92,63.83 65.72,63.83 65.62,63.73 65.62,61.77 65.52,61.67 65.32,61.67 65.23,61.77 65.23,63.73 65.13,63.83 64.93,63.83 64.83,63.73 64.83,61.77 64.73,61.67 64.53,61.67 64.43,61.77 64.43,63.73 64.33,63.83 64.14,63.83 64.04,63.73 64.04,61.77 63.94,61.67 63.74,61.67 63.64,61.77 63.64,63.73 63.54,63.83 63.34,63.83 63.24,63.73 63.24,61.77 63.15,61.67 62.95,61.67 62.85,61.77 62.85,63.73 62.75,63.83 62.55,63.83 62.45,63.73 62.45,61.77 62.35,61.67 62.15,61.67 62.06,61.77 62.06,63.73 61.96,63.83 61.76,63.83 61.66,63.73 61.66,62.59 61.56,62.49 61.19,62.49 61.09,62.4 61.09,62.2 61.19,62.1 61.56,62.1 61.66,62 61.66,61.77 61.56,61.67 61.37,61.67 60.93,61.24 60.93,60.5 60.84,60.4 60.55,60.4 60.42,60.53 60.42,61.22 60.32,61.32 60.13,61.32 60.03,61.22 60.03,60.58 59.93,60.48 59.73,60.48 59.63,60.58 59.63,61.29 59.53,61.39 59.36,61.39 59.23,61.27 59.23,60.58 59.14,60.48 58.77,60.48 58.67,60.58 58.67,60.86 58.58,60.96 58.38,60.96 58.28,60.86 58.28,60.58 58.18,60.48 57.78,60.48 57.66,60.6 57.66,61.47 58.07,61.88 v2(58.07,62.05)
FMC_A11: length 46.6
  TOP w0.152: U1.U8 v2(58.87,62.05) ; U2.H9 v2(66.89,63.23)
  ART06 w0.099: v2(58.87,62.05) 58.95,62.13 59.46,62.13 59.56,62.23 59.56,62.82 59.66,62.92 59.85,62.92 59.95,62.82 59.95,62.23 60.05,62.13 60.3,62.13 60.4,62.23 60.4,63.07 60.6,63.27 61.04,63.27 61.14,63.37 61.14,63.56 61.04,63.66 60.2,63.66 60.1,63.76 60.1,64.16 60.2,64.26 60.66,64.26 60.76,64.36 60.76,65.71 60.86,65.81 61.05,65.81 61.15,65.71 61.15,64.36 61.25,64.26 61.6,64.26 61.7,64.36 61.7,66.65 61.8,66.75 62,66.75 62.09,66.65 62.09,64.36 62.19,64.26 62.39,64.26 62.49,64.36 62.49,66.65 62.59,66.75 62.79,66.75 62.89,66.65 62.89,64.36 62.99,64.26 63.18,64.26 63.28,64.36 63.28,66.65 63.38,66.75 63.58,66.75 63.68,66.65 63.68,64.36 63.78,64.26 63.98,64.26 64.08,64.36 64.08,66.65 64.17,66.75 64.37,66.75 64.47,66.65 64.47,64.36 64.57,64.26 64.77,64.26 64.87,64.36 64.87,66.65 64.97,66.75 65.17,66.75 65.26,66.65 65.26,64.36 65.36,64.26 65.56,64.26 65.66,64.36 65.66,66.65 65.76,66.75 65.96,66.75 66.06,66.65 66.06,64.36 66.16,64.26 66.34,64.26 66.44,64.16 66.44,63.33 66.54,63.23 v2(66.89,63.23)
FMC_A12: length 40.3
  TOP w0.152: U1.H16 50.87,69.25 50.87,70.16 50.06,72.13 v2(50.06,72.21) ; v1(79.02,63.37) R1851.1
  ART06 w0.099: v2(50.06,72.21) 50.06,72.8 51.28,74.01 arc(52.86,75.07) 54.72,75.44 58.46,75.44 arc(59.01,75.33) 59.47,75.02 59.56,74.93 67.57,74.93 arc(69.21,74.6) 70.59,73.68 74.68,69.6 v1(79.02,63.37)
FMC_A14/FMC_BA0: length 46.5
  TOP w0.152: U1.H14 v2(51.67,67.65) ; v2(70.48,65.66) 69.25,64.43 U2.J7
  ART06 w0.099: v2(51.67,67.65) 51.18,68.13 51.18,69.02 51.28,69.12 51.54,69.12 51.64,69.22 51.64,69.42 51.54,69.52 51.28,69.52 51.18,69.61 51.18,69.81 51.28,69.91 51.54,69.91 51.64,70.01 51.64,70.21 51.54,70.31 51.28,70.31 51.18,70.41 51.18,70.61 51.28,70.7 51.98,70.7 52.15,70.87 52.15,72.72 52.83,73.41 61.47,73.41 61.57,73.31 61.57,72.11 61.67,72.01 64.33,72.01 64.43,71.91 64.43,71.55 64.53,71.45 64.73,71.45 64.83,71.55 64.83,72.16 64.92,72.26 65.12,72.26 65.22,72.16 65.22,71.55 65.32,71.45 65.52,71.45 65.62,71.55 65.62,72.16 65.72,72.26 65.92,72.26 66.01,72.16 66.01,71.55 66.11,71.45 66.31,71.45 66.41,71.55 66.41,72.16 66.51,72.26 66.71,72.26 66.81,72.16 66.81,71.55 66.91,71.45 67.1,71.45 67.2,71.55 67.2,72.16 67.3,72.26 67.5,72.26 67.6,72.16 67.6,71.55 67.7,71.45 67.9,71.45 68,71.55 68,72.16 68.09,72.26 68.29,72.26 68.39,72.16 68.39,71.55 68.49,71.45 68.69,71.45 68.79,71.55 68.79,72.16 68.89,72.26 69.08,72.26 69.18,72.16 69.18,71.55 69.28,71.45 69.48,71.45 69.58,71.55 69.58,72 69.68,72.1 69.91,72.1 71.27,70.74 71.27,65.76 71.17,65.66 v2(70.48,65.66)
FMC_A15/FMC_BA1: length 46.7
  TOP w0.152: U1.G14 v2(50.87,67.65) ; v2(71.69,65.63) 69.29,63.23 68.48,63.23 U2.H8
  ART06 w0.099: v2(71.69,65.63) 71.99,65.63 72.09,65.73 72.09,70.56 69.85,72.8 69.33,72.8 69.21,72.92 69.21,73.18 69.11,73.28 68.91,73.28 68.81,73.18 68.81,72.92 68.71,72.82 68.51,72.82 68.41,72.92 68.41,73.18 68.32,73.28 68.12,73.28 68.02,73.18 68.02,72.92 67.92,72.82 67.72,72.82 67.62,72.92 67.62,73.18 67.52,73.28 67.32,73.28 67.23,73.18 67.23,72.92 67.13,72.82 66.93,72.82 66.83,72.92 66.83,73.18 66.73,73.28 66.53,73.28 66.43,73.18 66.43,72.92 66.33,72.82 66.14,72.82 66.04,72.92 66.04,73.18 65.94,73.28 65.74,73.28 65.64,73.18 65.64,72.92 65.54,72.82 65.34,72.82 65.24,72.92 65.24,73.18 65.15,73.28 64.95,73.28 64.85,73.18 64.85,72.92 64.75,72.82 64.55,72.82 64.45,72.92 64.45,73.18 64.35,73.28 62.38,73.28 61.75,73.91 58.8,73.91 58.29,74.42 56.39,74.42 55.82,73.85 52.64,73.85 51.69,72.9 51.69,71.48 51.55,71.34 49.93,71.34 49.83,71.24 49.83,71.04 49.93,70.94 50.57,70.94 50.67,70.84 50.67,70.64 50.57,70.54 49.93,70.54 49.83,70.45 49.83,70.25 49.93,70.15 50.57,70.15 50.67,70.05 50.67,67.84 v2(50.87,67.65)
FMC_D0: length 47.5
  TOP w0.152: U2.R8 v2(68.49,69.63) ; U1.P16 v2(55.67,69.25)
  ART03 w0.114: v2(68.49,69.63) 67.95,69.09 67.56,69.09 67.28,69.37 67.28,70.36 67.11,70.54 66.59,70.54 66.48,70.42 66.48,70.19 66.36,70.08 66.13,70.08 66.02,70.19 66.02,70.42 65.91,70.54 65.68,70.54 65.56,70.42 65.56,70.19 65.45,70.08 65.22,70.08 65.11,70.19 65.11,70.42 64.99,70.54 64.76,70.54 64.65,70.42 64.65,70.19 64.53,70.08 64.31,70.08 64.19,70.19 64.19,70.42 64.08,70.54 63.85,70.54 63.73,70.42 63.73,70.19 63.62,70.08 63.39,70.08 63.28,70.19 63.28,70.42 63.16,70.54 62.93,70.54 62.82,70.42 62.82,70.19 62.71,70.08 62.48,70.08 62.36,70.19 62.36,70.42 62.25,70.54 62.02,70.54 61.91,70.42 61.91,70.19 61.79,70.08 61.56,70.08 61.45,70.19 61.45,71.56 61.33,71.68 61.13,71.68 60.99,71.54 60.99,70.19 60.88,70.08 60.65,70.08 60.53,70.19 60.53,70.42 60.42,70.54 60.08,70.54 59.97,70.65 59.97,71.56 59.86,71.68 59.31,71.68 59.16,71.53 58.85,71.53 58.73,71.41 58.73,70.55 58.62,70.43 58.39,70.43 58.28,70.55 58.28,71.41 58.16,71.53 57.93,71.53 57.82,71.41 57.82,70.55 57.7,70.43 57.48,70.43 57.36,70.55 57.36,71.41 57.25,71.53 57.02,71.53 56.9,71.41 56.9,70.55 56.79,70.43 56.56,70.43 56.45,70.55 56.45,71.41 56.33,71.53 55.79,71.53 55.67,71.41 55.67,70.55 55.56,70.43 55.33,70.43 55.19,70.57 55.19,71.84 55.08,71.96 54.81,71.96 54.7,71.84 54.7,70.55 54.59,70.43 54.33,70.43 54.22,70.55 54.22,71.84 54.1,71.96 53.84,71.96 53.72,71.84 53.72,70.57 53.61,70.46 52.13,70.46 52.02,70.35 52.02,70.15 50.92,69.05 50.92,68.89 51.13,68.68 51.33,68.68 52.27,69.62 52.9,69.62 53.28,69.25 53.61,69.25 53.72,69.36 53.72,69.79 53.84,69.9 54.07,69.9 54.18,69.79 54.18,69.36 54.29,69.25 v2(55.67,69.25)
FMC_D1: length 47.5
  TOP w0.152: U1.P15 v2(56.47,68.45) ; U2.N7 v2(69.29,68.03)
  ART03 w0.114: v2(69.29,68.03) 69.29,67.73 69.17,67.61 68.02,67.61 67.05,68.58 66.89,68.58 66.69,68.38 66.52,68.38 66.36,68.54 66.36,68.7 66.57,68.91 66.57,69.07 66.42,69.22 65.95,69.22 65.84,69.1 65.84,68.57 65.72,68.45 65.49,68.45 65.38,68.57 65.38,69.1 65.26,69.22 65.04,69.22 64.92,69.1 64.92,68.57 64.81,68.45 64.58,68.45 64.46,68.57 64.46,69.1 64.35,69.22 64.02,69.22 63.9,69.1 63.9,67.25 63.79,67.13 63.56,67.13 63.44,67.25 63.44,69.1 63.33,69.22 63.1,69.22 62.99,69.1 62.99,67.25 62.87,67.13 62.64,67.13 62.53,67.25 62.53,69.1 62.41,69.22 62.19,69.22 62.07,69.1 62.07,67.25 61.96,67.13 61.73,67.13 61.61,67.25 61.61,69.1 61.5,69.22 61.27,69.22 61.16,69.1 61.16,67.25 61.04,67.13 60.81,67.13 60.7,67.25 60.7,69.1 60.59,69.22 60.36,69.22 60.24,69.1 60.24,67.25 60.13,67.13 59.9,67.13 59.79,67.25 59.79,69.1 59.67,69.22 59.44,69.22 59.05,68.83 57.81,68.83 57.66,68.68 57.66,67.41 57.51,67.26 52.97,67.26 52.86,67.37 52.86,67.87 53.01,68.02 56.36,68.02 56.47,68.14 v2(56.47,68.45)
FMC_D2: length 47.4
  TOP w0.152: U1.D13 v2(48.47,66.05) ; U2.R9 v2(67.69,69.63)
  ART03 w0.114: v2(48.47,66.05) 48.06,66.46 48.06,66.66 47.94,66.77 47.43,66.77 47.32,66.89 47.32,67.12 47.43,67.23 47.94,67.23 48.06,67.34 48.06,67.67 47.94,67.79 47.84,67.79 47.73,67.9 47.73,68.13 47.84,68.25 47.94,68.25 48.06,68.36 48.06,69.22 48.27,69.43 48.76,69.43 48.87,69.55 48.87,69.77 48.76,69.89 48.27,69.89 48.16,70 48.16,70.23 48.27,70.35 48.76,70.35 48.87,70.46 48.87,70.89 49.76,71.78 50.09,71.78 50.21,71.67 50.21,70.87 50.09,70.76 49.62,70.76 49.5,70.64 49.5,70.42 49.62,70.3 50.09,70.3 50.21,70.19 50.21,69.79 50.32,69.67 50.55,69.67 50.66,69.79 50.66,71.69 50.78,71.81 51.01,71.81 51.12,71.69 51.12,70.35 51.23,70.23 51.46,70.23 51.58,70.35 51.58,72.28 51.69,72.39 51.99,72.39 52.1,72.28 52.1,71.16 52.22,71.04 52.45,71.04 52.56,71.16 52.56,72.28 52.68,72.39 53.49,72.39 53.6,72.5 53.6,72.86 53.71,72.97 53.94,72.97 54.06,72.86 54.06,72.5 54.17,72.39 54.4,72.39 54.52,72.5 54.52,72.86 54.63,72.97 54.86,72.97 54.97,72.86 54.97,72.5 55.09,72.39 55.3,72.39 55.73,71.96 56.08,71.96 56.26,72.14 61.72,72.14 62.1,71.75 62.1,71.25 62.36,70.99 64.45,70.99 64.56,71.11 64.56,71.39 64.68,71.5 64.91,71.5 65.02,71.39 65.02,71.11 65.14,70.99 65.36,70.99 65.48,71.11 65.48,71.39 65.59,71.5 65.82,71.5 65.94,71.39 65.94,71.11 66.05,70.99 66.28,70.99 66.39,71.11 66.39,71.39 66.51,71.5 66.74,71.5 66.85,71.39 66.85,71.11 66.97,70.99 67.57,70.99 67.69,70.88 67.69,70.68 67.8,70.56 68.36,70.56 68.48,70.45 68.48,70.22 68.36,70.11 67.8,70.11 67.69,69.99 v2(67.69,69.63)
FMC_D3: length 47.4
  TOP w0.152: U2.N8 v2(68.49,68.03) ; U1.E12 v2(48.47,65.25)
  ART03 w0.114: v2(68.49,68.03) 68.12,68.03 66.5,69.65 57.84,69.65 57.38,69.19 57.16,69.19 57.05,69.3 57.05,69.86 56.94,69.98 56.71,69.98 56.59,69.86 56.59,69.3 56.48,69.19 56.21,69.19 55.87,68.85 52.18,68.85 52.07,68.73 52.07,65 51.92,64.85 51.37,64.85 51.26,64.96 51.26,67.92 50.34,68.83 49.02,68.83 48.87,68.69 48.87,68.03 48.98,67.92 50.33,67.92 50.44,67.8 50.44,67.57 50.33,67.46 48.98,67.46 48.87,67.35 48.87,66.56 48.98,66.45 50.33,66.45 50.44,66.34 50.44,66.11 50.33,65.99 48.98,65.99 48.87,65.88 U1.E12 48.98,65.53 49.85,65.53 49.96,65.42 49.96,62.55 49.7,62.28 49.1,62.28 48.92,62.46 48.92,64.8 v2(48.47,65.25)
FMC_D4: length 47.6
  TOP w0.152: v2(66.09,68.03) 66.49,68.43 U2.P9 ; U1.U9 v2(58.87,63.65)
  ART03 w0.114: v2(66.09,68.03) 64.5,68.03 64.39,67.91 64.39,66.85 64.21,66.67 64.04,66.67 63.93,66.56 63.93,65.75 63.81,65.63 63.58,65.63 63.47,65.75 63.47,66.56 63.36,66.67 63.07,66.67 62.96,66.56 62.96,65.32 62.84,65.2 62.61,65.2 62.5,65.32 62.5,66.56 62.38,66.67 62.16,66.67 62.04,66.56 62.04,65.32 61.93,65.2 61.7,65.2 61.58,65.32 61.58,66.56 61.47,66.67 60.78,66.67 60.66,66.56 60.66,65.34 60.55,65.23 60.32,65.23 60.21,65.34 60.21,66.56 60.09,66.67 59.86,66.67 59.74,66.56 59.74,65.29 59.63,65.18 59.37,65.18 59.26,65.29 59.26,67.83 59.07,68.02 58.84,68.02 58.73,67.91 58.73,66.79 58.61,66.67 58.45,66.67 58.19,66.42 55.36,66.42 55.25,66.31 55.25,64.71 55.13,64.59 54.9,64.59 54.79,64.71 54.79,66.31 54.68,66.42 54.45,66.42 54.33,66.31 54.33,64.71 54.22,64.59 53.99,64.59 53.88,64.71 53.88,66.31 53.76,66.42 53,66.42 52.88,66.31 52.88,65.66 53,65.54 53.3,65.54 53.42,65.43 53.42,65.2 53.3,65.09 53,65.09 52.88,64.97 52.88,64.24 53.09,64.03 58.76,64.03 58.87,63.92 v2(58.87,63.65)
FMC_D5: length 47.4
  TOP w0.152: U2.M8 v2(68.49,67.23) ; U1.T9 v2(58.07,63.65)
  ART03 w0.114: v2(68.49,67.23) 67.9,67.23 67.49,67.64 66.52,67.64 66.4,67.51 65.94,67.51 65.83,67.4 65.83,66.54 65.71,66.42 65.48,66.42 65.37,66.54 65.37,67.4 65.25,67.51 64.94,67.51 64.82,67.4 64.82,65.66 65.09,65.39 65.09,62.17 64.97,62.05 64.75,62.05 64.63,62.17 64.63,64.63 64.52,64.74 64.18,64.74 64.07,64.63 64.07,62.17 63.96,62.05 63.73,62.05 63.61,62.17 63.61,64.63 63.5,64.74 63.27,64.74 63.16,64.63 63.16,62.17 63.04,62.05 62.81,62.05 62.7,62.17 62.7,64.63 62.58,64.74 62.36,64.74 62.24,64.63 62.24,62.17 62.13,62.05 61.9,62.05 61.78,62.17 61.78,64.63 61.67,64.74 61.34,64.74 61.23,64.63 61.23,63.31 61.11,63.2 60.88,63.2 60.77,63.31 60.77,64.63 60.65,64.74 60.37,64.74 60.25,64.63 60.25,62.27 60.14,62.15 59.91,62.15 59.8,62.27 59.8,64.63 59.68,64.74 59.44,64.74 59.28,64.59 59.28,62.88 59.17,62.76 58.64,62.76 58.52,62.88 58.52,63.19 v2(58.07,63.65)
FMC_D6: length 47.4
  TOP w0.152: U2.M7 v2(68.49,66.43) ; U1.P9 v2(56.47,63.65)
  ART03 w0.114: v2(68.49,66.43) 68.11,66.8 66.7,66.8 66.47,66.57 66.47,66.09 66.36,65.97 65.65,65.97 65.53,65.86 65.53,65.63 65.65,65.52 66.36,65.52 66.47,65.4 66.47,65.17 66.36,65.06 65.65,65.06 65.53,64.95 65.53,64.72 65.65,64.6 66.36,64.6 66.47,64.49 66.47,64.26 66.36,64.15 65.65,64.15 65.53,64.03 65.53,63.8 65.65,63.69 66.36,63.69 66.47,63.57 66.47,63.35 66.36,63.23 65.65,63.23 65.53,63.12 65.53,62.89 65.65,62.77 66.36,62.77 66.47,62.66 66.47,62.43 66.36,62.32 65.65,62.32 65.53,62.2 65.53,61.97 65.65,61.86 66.36,61.86 66.47,61.75 66.47,61.38 66.36,61.26 65.93,61.26 65.81,61.15 65.81,60.01 65.7,59.89 65.47,59.89 65.36,60.01 65.36,61.15 65.24,61.26 65.01,61.26 64.9,61.15 64.9,60.01 64.78,59.89 64.56,59.89 64.44,60.01 64.44,61.15 64.33,61.26 64.1,61.26 63.98,61.15 63.98,60.01 63.87,59.89 63.64,59.89 63.53,60.01 63.53,61.15 63.41,61.26 63.18,61.26 63.07,61.15 63.07,60.01 62.95,59.89 62.73,59.89 62.61,60.01 62.61,61.15 62.5,61.26 62.27,61.26 62.15,61.15 62.15,60.01 62.04,59.89 61.81,59.89 61.7,60.01 61.7,61.15 61.58,61.26 61.35,61.26 61.24,61.15 61.24,60.49 61.13,60.38 60.9,60.38 60.78,60.49 60.78,61.15 60.67,61.26 60.44,61.26 60.33,61.15 60.33,60.01 60.21,59.89 59.98,59.89 59.87,60.01 59.87,61.15 59.75,61.26 59.53,61.26 59.41,61.15 59.41,60.01 59.3,59.89 59.07,59.89 58.95,60.01 58.95,61.15 58.84,61.26 58.59,61.26 58.47,61.38 58.47,62.36 58.14,62.69 58.14,62.99 58.01,63.12 56.7,63.12 56.47,63.35 v2(56.47,63.65)
FMC_D7: length 47.5
  TOP w0.152: U2.L8 v2(67.68,65.63) ; U1.N9 v2(55.67,63.65)
  ART03 w0.114: v2(55.67,63.65) U1.N9 50.55,63.25 50.39,63.09 50.39,62.66 50.6,62.46 56.69,62.46 56.85,62.31 56.85,61.93 57.1,61.67 57.48,61.67 57.68,61.47 57.68,60.86 57.76,60.78 58.39,60.78 58.55,60.63 58.55,60.38 58.43,60.27 57.85,60.27 57.73,60.16 57.73,59.93 57.85,59.81 58.43,59.81 58.55,59.7 58.55,59.54 58.62,59.46 58.9,59.46 59.02,59.35 59.02,58.99 59.13,58.88 59.36,58.88 59.47,58.99 59.47,59.35 59.59,59.46 59.82,59.46 59.93,59.35 59.93,58.99 60.04,58.88 60.27,58.88 60.39,58.99 60.39,59.35 60.5,59.46 61.64,59.46 61.76,59.35 61.76,58.99 61.87,58.88 62.1,58.88 62.22,58.99 62.22,59.35 62.33,59.46 62.56,59.46 62.67,59.35 62.67,58.99 62.79,58.88 63.02,58.88 63.13,58.99 63.13,59.35 63.24,59.46 63.47,59.46 63.59,59.35 63.59,58.99 63.7,58.88 63.93,58.88 64.05,58.99 64.05,59.35 64.16,59.46 64.39,59.46 64.5,59.35 64.5,58.99 64.62,58.88 64.85,58.88 64.96,58.99 64.96,59.35 65.07,59.46 65.3,59.46 65.42,59.35 65.42,58.99 65.53,58.88 65.76,58.88 65.87,58.99 65.87,59.35 65.99,59.46 66.42,59.46 66.57,59.61 67.17,59.61 67.28,59.5 67.28,58.92 67.4,58.8 67.63,58.8 67.74,58.92 67.74,59.5 67.86,59.61 67.94,59.61 68.07,59.74 68.07,60.14 67.96,60.25 67.42,60.25 67.31,60.37 67.31,60.59 67.42,60.71 67.96,60.71 68.07,60.82 68.07,61.05 67.96,61.17 67.42,61.17 67.31,61.28 67.31,61.51 67.42,61.62 67.96,61.62 68.07,61.74 68.07,61.97 67.96,62.08 67.42,62.08 67.31,62.19 67.31,62.42 67.42,62.54 67.96,62.54 68.07,62.65 68.07,62.88 67.96,62.99 67.42,62.99 67.31,63.11 67.31,63.34 67.42,63.45 67.96,63.45 68.07,63.57 68.07,65.24 v2(67.68,65.63)
FMC_D8: length 45.7
  TOP w0.152: U1.P10 v2(56.47,64.45) ; U2.L2 v2(72.49,66.43)
  ART08 w0.114: v2(56.47,64.45) 56.87,64.05 57.4,64.05 57.66,64.3 57.66,64.64 57.86,64.85 58.27,64.85 58.47,65.05 58.47,65.43 58.7,65.66 59.56,65.66 59.74,65.48 59.74,64.48 59.86,64.36 60.11,64.36 60.22,64.48 60.22,65.57 60.34,65.68 60.56,65.68 60.68,65.57 60.68,64.48 60.79,64.36 61.02,64.36 61.14,64.48 61.14,65.57 61.25,65.68 61.48,65.68 61.59,65.57 61.59,64.48 61.71,64.36 61.94,64.36 62.05,64.48 62.05,65.57 62.16,65.68 62.39,65.68 62.51,65.57 62.51,64.48 62.62,64.36 62.85,64.36 62.96,64.48 62.96,65.57 63.08,65.68 63.31,65.68 63.42,65.57 63.42,64.48 63.54,64.36 63.76,64.36 63.88,64.48 63.88,65.57 63.99,65.68 64.22,65.68 64.34,65.57 64.34,64.48 64.45,64.36 64.68,64.36 64.79,64.48 64.79,65.57 64.91,65.68 65.14,65.68 65.25,65.57 65.25,64.48 65.36,64.36 65.59,64.36 65.71,64.48 65.71,65.57 65.82,65.68 66.05,65.68 66.16,65.57 66.16,63.74 66.28,63.63 67.38,63.63 67.49,63.51 67.49,63.36 67.61,63.25 67.84,63.25 67.95,63.36 67.95,63.51 68.07,63.63 68.3,63.63 68.41,63.51 68.41,63.36 68.52,63.25 68.75,63.25 68.87,63.36 68.87,63.82 68.98,63.93 69.21,63.93 69.32,63.82 69.32,63.36 69.44,63.25 69.67,63.25 69.78,63.36 69.78,63.82 69.9,63.93 70.12,63.93 70.24,63.82 70.24,63.36 70.35,63.25 70.58,63.25 70.7,63.36 70.7,63.82 70.81,63.93 71.04,63.93 71.15,63.82 71.15,63.36 71.27,63.25 71.5,63.25 71.61,63.36 71.61,63.82 71.72,63.93 71.95,63.93 72.07,63.82 72.07,63.36 72.18,63.25 72.41,63.25 72.52,63.36 72.52,63.51 72.64,63.63 72.83,63.63 72.95,63.74 72.95,65.96 v2(72.49,66.43)
FMC_D9: length 45.6
  TOP w0.152: U1.R10 v2(57.27,64.45) ; v2(71.69,67.23) U2.M3
  ART08 w0.114: v2(57.27,64.45) 57.27,64.71 57.66,65.1 57.66,65.41 57.9,65.65 58.24,65.65 58.47,65.87 58.47,66.22 58.8,66.55 58.8,67.13 58.92,67.25 59.15,67.25 59.27,67.13 59.27,66.15 59.38,66.04 59.61,66.04 59.73,66.15 59.73,67.12 59.84,67.23 60.07,67.23 60.18,67.12 60.18,66.15 60.3,66.04 60.53,66.04 60.64,66.15 60.64,67.12 60.75,67.23 61.43,67.23 61.54,67.12 61.54,66.15 61.66,66.04 61.95,66.04 62.06,66.15 62.06,67.14 62.18,67.26 62.41,67.26 62.52,67.14 62.52,66.15 62.63,66.04 62.86,66.04 62.98,66.15 62.98,67.14 63.09,67.26 63.32,67.26 63.43,67.14 63.43,66.15 63.55,66.04 63.78,66.04 63.89,66.15 63.89,67.14 64.01,67.26 64.23,67.26 64.35,67.14 64.35,66.15 64.46,66.04 64.69,66.04 64.81,66.15 64.81,67.14 64.92,67.26 65.15,67.26 65.26,67.14 65.26,66.15 65.38,66.04 65.61,66.04 65.72,66.15 65.72,67.14 65.83,67.26 66.06,67.26 66.18,67.14 66.18,66.15 66.29,66.04 66.38,66.04 66.5,65.93 66.5,64.57 66.65,64.41 66.96,64.41 67.07,64.53 67.07,65.14 67.18,65.25 67.41,65.25 67.53,65.14 67.53,64.53 67.64,64.41 67.87,64.41 67.98,64.53 67.98,65.14 68.1,65.25 68.33,65.25 68.44,65.14 68.44,64.53 68.56,64.41 68.78,64.41 68.9,64.53 68.9,65.14 69.01,65.25 69.24,65.25 69.36,65.14 69.36,64.53 69.47,64.41 69.7,64.41 69.81,64.53 69.81,65.14 69.93,65.25 70.16,65.25 70.27,65.14 70.27,64.53 70.38,64.41 70.61,64.41 70.73,64.53 70.73,65.14 70.84,65.25 71.07,65.25 71.19,65.14 71.19,64.53 71.3,64.41 71.93,64.41 72.09,64.57 72.09,66.83 v2(71.69,67.23)
FMC_D10: length 45.6
  TOP w0.152: U1.T10 v2(58.07,64.45) ; U2.M2 v2(72.49,67.23)
  ART08 w0.114: v2(72.49,67.23) 73.19,67.23 73.3,67.11 73.3,62.95 73.19,62.84 66.13,62.84 66.01,62.73 66.01,62.27 65.9,62.15 65.6,62.15 65.49,62.27 65.49,63.82 65.37,63.93 65.14,63.93 65.03,63.82 65.03,62.27 64.91,62.15 64.69,62.15 64.57,62.27 64.57,63.82 64.46,63.93 64.23,63.93 64.11,63.82 64.11,62.27 64,62.15 63.77,62.15 63.66,62.27 63.66,63.82 63.54,63.93 63.31,63.93 63.2,63.82 63.2,62.27 63.09,62.15 62.86,62.15 62.74,62.27 62.74,63.82 62.63,63.93 62.4,63.93 62.29,63.82 62.29,62.27 62.17,62.15 61.94,62.15 61.83,62.27 61.83,63.82 61.71,63.93 61.49,63.93 61.37,63.82 61.37,62.27 61.26,62.15 60.52,62.15 60.38,62.29 60.38,63.84 60.26,63.96 60.03,63.96 59.92,63.84 59.92,62.27 59.8,62.15 59.47,62.15 59.36,62.27 59.36,62.49 59.25,62.6 58.79,62.6 58.67,62.72 58.67,62.95 58.79,63.06 59.25,63.06 59.36,63.17 59.36,64.72 59.23,64.85 58.67,64.85 58.27,64.45 v2(58.07,64.45)
FMC_D11: length 45.6
  TOP w0.152: U2.P1 v2(74.08,68.83) ; U1.U10 v2(58.87,64.45)
  ART08 w0.114: v2(74.08,68.83) 73.66,68.4 73.66,62.17 73.52,62.03 66.7,62.03 65.89,61.22 65.73,61.22 65.53,61.43 65.36,61.43 65.2,61.27 65.2,61.1 65.41,60.9 65.41,60.74 65.15,60.48 64.64,60.48 64.53,60.59 64.53,61.18 64.42,61.29 64.19,61.29 64.07,61.18 64.07,60.59 63.96,60.48 63.73,60.48 63.62,60.59 63.62,61.18 63.5,61.29 63.27,61.29 63.16,61.18 63.16,60.59 63.04,60.48 62.82,60.48 62.7,60.59 62.7,61.18 62.59,61.29 62.36,61.29 62.24,61.18 62.24,60.59 62.13,60.48 61.9,60.48 61.79,60.59 61.79,61.18 61.67,61.29 61.44,61.29 61.33,61.18 61.33,60.59 61.22,60.48 60.99,60.48 60.87,60.59 60.87,61.18 60.76,61.29 60.53,61.29 60.42,61.18 60.42,60.59 60.3,60.48 60.07,60.48 59.96,60.59 59.96,61.18 59.84,61.29 59.62,61.29 59.5,61.18 59.5,60.59 59.39,60.48 59.16,60.48 59.04,60.59 59.04,61.18 58.93,61.29 58.7,61.29 58.59,61.18 58.59,60.59 58.47,60.48 58.04,60.48 57.61,60.05 57.05,60.05 56.87,60.22 56.87,62.51 56.77,62.61 55.69,62.61 55.58,62.73 55.58,63.07 55.75,63.25 57.28,63.25 57.4,63.13 57.4,62.57 57.51,62.46 57.74,62.46 57.85,62.57 57.85,63.13 57.97,63.25 58.34,63.25 58.47,63.37 U1.U10 v2(58.87,64.45)
FMC_D12: length 45.6
  TOP w0.152: U1.R11 v2(57.27,65.25) ; U2.N2 v2(72.49,68.03)
  ART08 w0.114: v2(72.49,68.03) 72.1,67.64 71.4,67.64 71.27,67.51 71.27,66.17 71.15,66.04 70.86,66.04 70.74,66.15 70.74,68.21 70.6,68.35 70.4,68.35 70.29,68.24 70.29,67.46 70.17,67.34 69.08,67.34 68.96,67.23 68.96,67 69.08,66.88 70.17,66.88 70.29,66.77 70.29,66.15 70.17,66.04 67.46,66.04 67.31,66.19 67.31,66.54 67.42,66.65 67.91,66.65 68.02,66.77 68.02,66.99 67.91,67.11 67.42,67.11 67.31,67.22 67.31,67.45 67.42,67.57 67.91,67.57 68.02,67.68 68.02,67.91 67.91,68.02 67.42,68.02 67.31,68.14 67.31,68.75 67.2,68.86 65.72,68.86 65.61,68.75 65.61,67.79 65.46,67.64 65.26,67.64 65.14,67.75 65.14,68.75 65.03,68.86 64.8,68.86 64.69,68.75 64.69,67.75 64.57,67.64 64.34,67.64 64.23,67.75 64.23,68.75 64.11,68.86 63.89,68.86 63.77,68.75 63.77,67.75 63.66,67.64 63.43,67.64 63.31,67.75 63.31,68.75 63.2,68.86 62.97,68.86 62.86,68.75 62.86,67.75 62.74,67.64 62.51,67.64 62.4,67.75 62.4,68.75 62.29,68.86 62.06,68.86 61.94,68.75 61.94,67.75 61.83,67.64 61.6,67.64 61.49,67.75 61.49,68.75 61.37,68.86 61.14,68.86 61.03,68.75 61.03,67.75 60.91,67.64 60.69,67.64 60.57,67.75 60.57,68.75 60.46,68.86 60.23,68.86 60.11,68.75 60.11,67.75 60,67.64 58.72,67.64 58.47,67.39 58.47,66.6 58.32,66.45 57.82,66.45 57.66,66.28 57.66,65.86 57.27,65.47 v2(57.27,65.25)
FMC_D13: length 45.6
  TOP w0.152: U2.R1 v2(74.08,69.63) ; U1.U16 v2(58.87,69.25)
  ART08 w0.114: v2(74.08,69.63) 74.08,70.52 71.97,72.63 71.03,72.63 70.92,72.75 70.92,73.42 70.81,73.53 70.58,73.53 70.46,73.42 70.46,72.75 70.35,72.63 70.12,72.63 70.01,72.75 70.01,73.42 69.89,73.53 69.66,73.53 69.55,73.42 69.55,72.75 69.43,72.63 69.21,72.63 69.09,72.75 69.09,73.42 68.98,73.53 68.75,73.53 68.63,73.42 68.63,72.75 68.52,72.63 68.29,72.63 68.18,72.75 68.18,73.42 68.06,73.53 67.83,73.53 67.72,73.42 67.72,72.75 67.61,72.63 67.38,72.63 67.26,72.75 67.26,73.42 67.15,73.53 66.92,73.53 66.81,73.42 66.81,72.75 66.69,72.63 66.46,72.63 66.35,72.75 66.35,73.42 66.23,73.53 66.01,73.53 65.89,73.42 65.89,72.75 65.78,72.63 65.55,72.63 65.43,72.75 65.43,73.42 65.32,73.53 65.09,73.53 64.98,73.42 64.98,72.75 64.86,72.63 64.6,72.63 64.03,73.2 58.59,73.2 58.47,73.09 58.47,73.07 58.36,72.95 56.45,72.95 56.34,72.84 56.34,72.61 56.45,72.49 58.36,72.49 58.47,72.38 58.47,72.15 58.36,72.04 56.45,72.04 56.34,71.92 56.34,71.69 56.45,71.58 58.36,71.58 58.47,71.47 58.47,71.24 58.36,71.12 56.45,71.12 56.34,71.01 56.34,70.78 56.45,70.67 58.36,70.67 58.47,70.55 58.47,69.64 v2(58.87,69.25)
FMC_D14: length 45.7
  TOP w0.152: U1.T17 v2(58.07,70.05) ; U2.N3 v2(71.69,68.03)
  ART08 w0.114: v2(58.07,70.05) 57.77,70.05 57.66,69.93 57.66,69.72 57.54,69.6 56.55,69.6 56.44,69.49 56.44,69.26 56.55,69.15 57.54,69.15 57.66,69.03 57.66,68.2 57.81,68.05 59.31,68.05 59.64,68.38 59.64,70.47 59.75,70.59 60.06,70.59 60.17,70.47 60.17,69.35 60.29,69.24 60.58,69.24 60.69,69.35 60.69,70.45 60.8,70.56 61.03,70.56 61.15,70.45 61.15,69.35 61.26,69.24 61.49,69.24 61.6,69.35 61.6,70.45 61.72,70.56 61.95,70.56 62.06,70.45 62.06,69.35 62.18,69.24 62.4,69.24 62.52,69.35 62.52,70.45 62.63,70.56 62.86,70.56 62.98,70.45 62.98,69.35 63.09,69.24 63.32,69.24 63.43,69.35 63.43,70.45 63.55,70.56 63.78,70.56 63.89,70.45 63.89,69.35 64,69.24 64.23,69.24 64.35,69.35 64.35,70.45 64.46,70.56 64.69,70.56 64.8,70.45 64.8,69.35 64.92,69.24 65.15,69.24 65.26,69.35 65.26,70.45 65.38,70.56 65.6,70.56 65.72,70.45 65.72,69.35 65.83,69.24 66.06,69.24 66.18,69.35 66.18,70.45 66.29,70.56 66.52,70.56 66.63,70.45 66.63,69.35 66.75,69.24 69.59,69.24 69.71,69.35 69.71,70.35 69.82,70.46 70.05,70.46 70.16,70.35 70.16,69.35 70.28,69.24 70.51,69.24 70.62,69.35 70.62,70.35 70.74,70.46 70.96,70.46 71.08,70.35 71.08,69.35 71.19,69.24 71.95,69.24 72.06,69.13 72.06,68.4 v2(71.69,68.03)
